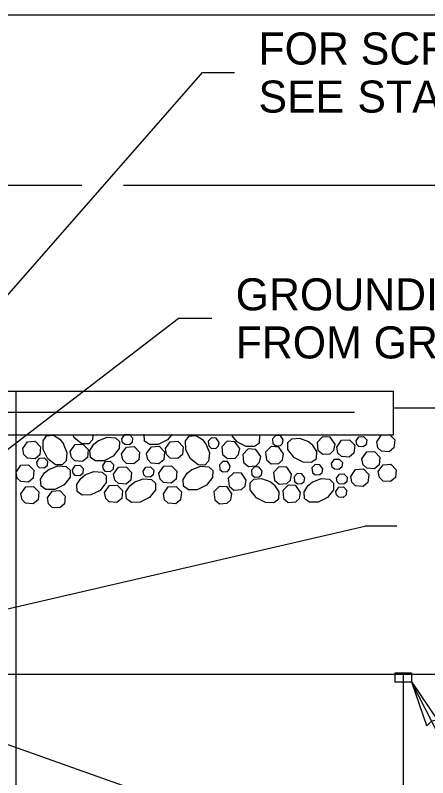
# Model space of a CAD drawing. Extents: x 99862 to 103680, y 99470 to 105076.
# Drawn here: x 100784.9 to 100991, y 104694.7 to 105075.5 of the extents above; entities that cross this region are included whole.
import ezdxf

# ---------------------------------------------------------------- set-up
doc = ezdxf.new("R2010")
doc.units = 0
for name, color, linetype in [('Level 1', 7, 'Continuous'), ('Level 12', 7, 'Continuous'), ('Level 15', 7, 'Continuous'), ('Level 16', 7, 'Continuous'), ('Level 20', 7, 'Continuous'), ('Level 3', 7, 'Continuous'), ('Level 33', 7, 'Continuous'), ('Level 6', 7, 'Continuous'), ('Level 9', 7, 'Continuous')]:
    doc.layers.add(name, color=color, linetype=linetype)

msp = doc.modelspace()

# ---------------------------------------------------------------- linework, layer by layer
at = {"layer": 'Level 1'}
msp.add_line((100343.64, 104887.78), (100943.64, 104887.78), dxfattribs=at)
msp.add_lwpolyline([(99862, 102999.5), (103151, 102999.5), (103151, 105075.5), (99862, 105075.5)], close=True, dxfattribs=at)
at = {"layer": 'Level 12'}
msp.add_lwpolyline([(100313.64, 104887.78), (100973.64, 104887.78), (100973.64, 104865.78), (100313.64, 104865.78)], close=True, dxfattribs=at)
at = {"layer": 'Level 15'}
for p, q in [((100760.56, 104912.34), (100878.43, 105046.89)), ((100878.43, 105046.89), (100894.43, 105046.89)), ((100675.26, 104777.56), (100866.25, 104924.12)), ((100883.04, 104924.12), (100866.25, 104924.12)), ((100706.3, 104761.84), (100959.51, 104820.29)), ((100975.51, 104820.29), (100959.51, 104820.29)), ((100693.13, 104742.4), (101012.2, 104629.58)), ((100982.9, 104742.4), (101012.2, 104684.93))]:
    msp.add_line(p, q, dxfattribs=at)
for points in [[(100617.42, 104990.65), (100818.24, 104990.65)], [(100839.05, 104990.65), (101204.8, 104990.65), (101435.21, 104856.14)]]:
    msp.add_lwpolyline(points, dxfattribs=at)
msp.add_lwpolyline([(100982.99, 104742.44), (100995.94, 104723.41), (100992.8, 104723.01), (100990.62, 104720.72)], close=True, dxfattribs=at)
at = {"layer": 'Level 16'}
for p, q in [((100785.34, 104392.87), (100785.34, 104887.78)), ((100246.62, 104746.39), (101041.91, 104746.39)), ((100978.89, 104392.86), (100978.89, 104746.39))]:
    msp.add_line(p, q, dxfattribs=at)
msp.add_lwpolyline([(100974.66, 104747.08), (100982.9, 104747.08), (100982.9, 104742.4), (100974.66, 104742.4)], close=True, dxfattribs=at)
at = {"layer": 'Level 3'}
for points in [[(100838.18, 104864), (100839.63, 104866.07), (100841.95, 104866.2), (100843.56, 104864.53), (100843.33, 104862.19), (100841.9, 104861), (100839.61, 104861.16), (100838.53, 104862.21), (100838.18, 104864)], [(100863.29, 104866.37), (100861.01, 104863.47), (100856.37, 104861.15), (100852.01, 104861.07), (100849.55, 104862.82), (100849.31, 104866.3), (100849.36, 104866.37)], [(100965.55, 104862.56), (100967.96, 104866), (100971.83, 104866.22), (100974.51, 104863.43), (100974.13, 104859.53), (100971.74, 104857.55), (100967.92, 104857.82), (100966.13, 104859.56), (100965.55, 104862.56)], [(100788.61, 104859.07), (100791.03, 104862.52), (100794.89, 104862.74), (100797.58, 104859.95), (100797.19, 104856.05), (100794.8, 104854.06), (100790.99, 104854.34), (100789.19, 104856.08), (100788.61, 104859.07)], [(100808.85, 104861.63), (100810.64, 104857.1), (100810.28, 104852.94), (100808.41, 104850.97), (100805.03, 104851.03), (100801.19, 104854.03), (100798.88, 104858.67), (100798.8, 104863.04), (100800.55, 104865.5), (100804.03, 104865.73), (100807.14, 104863.74), (100808.96, 104861.45)], [(100823.63, 104865.43), (100823.46, 104863.46), (100821.58, 104861.48), (100818.21, 104861.54), (100814.37, 104864.54), (100813.93, 104865.43)], [(100826.29, 104863.02), (100830.82, 104864.82), (100834.98, 104864.46), (100836.95, 104862.58), (100836.89, 104859.2), (100833.89, 104855.37), (100829.26, 104853.05), (100824.89, 104852.97), (100822.43, 104854.72), (100822.19, 104858.2), (100824.19, 104861.31), (100826.48, 104863.14)], [(100859.89, 104859.1), (100862.31, 104862.55), (100866.17, 104862.77), (100868.86, 104859.98), (100868.47, 104856.08), (100866.08, 104854.1), (100862.27, 104854.37), (100860.48, 104856.11), (100859.89, 104859.1)], [(100880.08, 104861.52), (100881.88, 104856.99), (100881.52, 104852.83), (100879.64, 104850.85), (100876.26, 104850.92), (100872.43, 104853.92), (100870.11, 104858.55), (100870.03, 104862.92), (100871.78, 104865.38), (100875.26, 104865.61), (100878.37, 104863.62), (100880.2, 104861.33)], [(100886.72, 104862.22), (100885.27, 104864.29), (100882.95, 104864.42), (100881.34, 104862.75), (100881.57, 104860.41), (100883.01, 104859.22), (100885.3, 104859.38), (100886.37, 104860.43), (100886.72, 104862.22)], [(100897.1, 104859.1), (100894.68, 104862.55), (100890.82, 104862.77), (100888.13, 104859.98), (100888.52, 104856.08), (100890.91, 104854.1), (100894.72, 104854.37), (100896.52, 104856.11), (100897.1, 104859.1)], [(100893.16, 104865.55), (100895.43, 104862.64), (100900.07, 104860.32), (100904.44, 104860.25), (100906.9, 104861.99), (100907.13, 104865.48), (100907.08, 104865.55)], [(100918.81, 104863.5), (100917.36, 104865.57), (100915.04, 104865.7), (100913.43, 104864.03), (100913.66, 104861.69), (100915.1, 104860.49), (100917.39, 104860.66), (100918.46, 104861.7), (100918.81, 104863.5)], [(100931.54, 104862.41), (100927.02, 104864.2), (100922.86, 104863.84), (100920.88, 104861.97), (100920.94, 104858.59), (100923.95, 104854.76), (100928.58, 104852.44), (100932.95, 104852.36), (100935.41, 104854.11), (100935.64, 104857.59), (100933.65, 104860.7), (100931.36, 104862.53)], [(100944.7, 104861.28), (100942.28, 104864.73), (100938.42, 104864.95), (100935.73, 104862.16), (100936.12, 104858.26), (100938.51, 104856.27), (100942.32, 104856.55), (100944.12, 104858.29), (100944.7, 104861.28)], [(100945.55, 104859.88), (100947.97, 104863.33), (100951.83, 104863.55), (100954.52, 104860.76), (100954.13, 104856.86), (100951.74, 104854.87), (100947.93, 104855.15), (100946.14, 104856.89), (100945.55, 104859.88)], [(100955.15, 104862.97), (100956.6, 104865.03), (100958.92, 104865.16), (100960.53, 104863.49), (100960.3, 104861.15), (100958.86, 104859.96), (100956.57, 104860.13), (100955.5, 104861.17), (100955.15, 104862.97)], [(100812.33, 104857.71), (100814.76, 104861.16), (100818.62, 104861.38), (100821.31, 104858.59), (100820.92, 104854.69), (100818.53, 104852.71), (100814.71, 104852.98), (100812.92, 104854.72), (100812.34, 104857.71)], [(100838.02, 104856.44), (100840.44, 104859.88), (100844.3, 104860.1), (100846.99, 104857.32), (100846.6, 104853.41), (100844.21, 104851.43), (100840.4, 104851.7), (100838.6, 104853.45), (100838.02, 104856.44)], [(100850.5, 104856.58), (100852.92, 104860.02), (100856.79, 104860.24), (100859.47, 104857.46), (100859.09, 104853.56), (100856.7, 104851.57), (100852.88, 104851.85), (100851.09, 104853.59), (100850.51, 104856.58)], [(100907.6, 104855.24), (100905.18, 104858.69), (100901.31, 104858.91), (100898.63, 104856.12), (100899.01, 104852.22), (100901.4, 104850.23), (100905.22, 104850.51), (100907.01, 104852.25), (100907.59, 104855.24)], [(100918.98, 104856.44), (100916.56, 104859.88), (100912.69, 104860.1), (100910.01, 104857.32), (100910.39, 104853.41), (100912.78, 104851.43), (100916.6, 104851.7), (100918.39, 104853.45), (100918.97, 104856.44)], [(100795.63, 104852.3), (100797.08, 104854.36), (100799.4, 104854.49), (100801.01, 104852.82), (100800.78, 104850.48), (100799.34, 104849.29), (100797.06, 104849.46), (100795.98, 104850.5), (100795.63, 104852.3)], [(100958.13, 104853.99), (100960.54, 104857.44), (100964.41, 104857.66), (100967.1, 104854.87), (100966.71, 104850.97), (100964.32, 104848.98), (100960.51, 104849.26), (100958.71, 104851), (100958.13, 104853.99)], [(100785.27, 104847.4), (100787.7, 104850.85), (100791.56, 104851.07), (100794.25, 104848.28), (100793.86, 104844.38), (100791.47, 104842.4), (100787.65, 104842.67), (100785.86, 104844.41), (100785.28, 104847.4)], [(100813.44, 104848.57), (100814.89, 104850.63), (100817.21, 104850.77), (100818.82, 104849.09), (100818.59, 104846.75), (100817.15, 104845.56), (100814.87, 104845.73), (100813.79, 104846.77), (100813.44, 104848.57)], [(100828.59, 104850.56), (100830.04, 104852.63), (100832.36, 104852.76), (100833.97, 104851.09), (100833.74, 104848.75), (100832.31, 104847.55), (100830.02, 104847.72), (100828.94, 104848.77), (100828.59, 104850.56)], [(100892.34, 104850.55), (100890.89, 104852.61), (100888.57, 104852.74), (100886.96, 104851.07), (100887.19, 104848.73), (100888.62, 104847.54), (100890.91, 104847.71), (100891.99, 104848.75), (100892.34, 104850.55)], [(100938.53, 104848.97), (100937.08, 104851.04), (100934.76, 104851.17), (100933.15, 104849.5), (100933.38, 104847.16), (100934.81, 104845.96), (100937.1, 104846.13), (100938.18, 104847.18), (100938.53, 104848.97)], [(100942.94, 104851.68), (100944.39, 104853.75), (100946.71, 104853.88), (100948.32, 104852.21), (100948.09, 104849.87), (100946.65, 104848.67), (100944.36, 104848.84), (100943.29, 104849.89), (100942.94, 104851.68)], [(100966.27, 104847.63), (100968.69, 104851.07), (100972.55, 104851.29), (100975.24, 104848.51), (100974.85, 104844.6), (100972.46, 104842.62), (100968.65, 104842.89), (100966.85, 104844.64), (100966.27, 104847.63)], [(100801.66, 104848.72), (100806.18, 104850.51), (100810.34, 104850.15), (100812.32, 104848.27), (100812.26, 104844.9), (100809.26, 104841.06), (100804.62, 104838.75), (100800.25, 104838.67), (100797.79, 104840.42), (100797.56, 104843.9), (100799.56, 104847.01), (100801.84, 104848.83)], [(100819.71, 104845.92), (100824.24, 104847.71), (100828.4, 104847.35), (100830.37, 104845.47), (100830.31, 104842.1), (100827.31, 104838.26), (100822.67, 104835.94), (100818.3, 104835.87), (100815.84, 104837.62), (100815.61, 104841.1), (100817.61, 104844.21), (100819.89, 104846.03)], [(100834.05, 104846.36), (100836.47, 104849.8), (100840.33, 104850.02), (100843.02, 104847.24), (100842.63, 104843.33), (100840.24, 104841.35), (100836.43, 104841.62), (100834.63, 104843.37), (100834.05, 104846.36)], [(100848.73, 104847.77), (100850.18, 104849.84), (100852.5, 104849.97), (100854.12, 104848.3), (100853.88, 104845.96), (100852.45, 104844.77), (100850.16, 104844.93), (100849.08, 104845.98), (100848.73, 104847.77)], [(100856.66, 104846.88), (100859.08, 104850.32), (100862.95, 104850.54), (100865.63, 104847.76), (100865.25, 104843.86), (100862.86, 104841.87), (100859.04, 104842.15), (100857.25, 104843.89), (100856.67, 104846.88)], [(100872.9, 104848.56), (100877.43, 104850.36), (100881.59, 104850), (100883.57, 104848.12), (100883.51, 104844.74), (100880.51, 104840.91), (100875.87, 104838.59), (100871.5, 104838.51), (100869.04, 104840.26), (100868.81, 104843.74), (100870.8, 104846.85), (100873.09, 104848.68)], [(100900.33, 104843.39), (100897.91, 104846.84), (100894.04, 104847.06), (100891.36, 104844.27), (100891.75, 104840.37), (100894.13, 104838.38), (100897.95, 104838.66), (100899.75, 104840.4), (100900.33, 104843.39)], [(100908.26, 104847.77), (100906.81, 104849.84), (100904.49, 104849.97), (100902.88, 104848.3), (100903.11, 104845.96), (100904.54, 104844.77), (100906.83, 104844.93), (100907.91, 104845.98), (100908.26, 104847.77)], [(100922.95, 104846.36), (100920.52, 104849.8), (100916.66, 104850.02), (100913.97, 104847.24), (100914.36, 104843.33), (100916.75, 104841.35), (100920.57, 104841.62), (100922.36, 104843.37), (100922.94, 104846.36)], [(100952.54, 104845.25), (100954.96, 104848.7), (100958.83, 104848.92), (100961.51, 104846.13), (100961.12, 104842.23), (100958.74, 104840.24), (100954.92, 104840.52), (100953.13, 104842.26), (100952.54, 104845.25)], [(100844.31, 104842.26), (100848.83, 104844.05), (100852.99, 104843.69), (100854.97, 104841.81), (100854.91, 104838.44), (100851.91, 104834.6), (100847.27, 104832.28), (100842.9, 104832.21), (100840.44, 104833.95), (100840.21, 104837.44), (100842.2, 104840.55), (100844.49, 104842.37)], [(100912.69, 104842.26), (100908.16, 104844.05), (100904, 104843.69), (100902.02, 104841.81), (100902.09, 104838.44), (100905.09, 104834.6), (100909.72, 104832.28), (100914.09, 104832.21), (100916.55, 104833.95), (100916.79, 104837.44), (100914.79, 104840.55), (100912.5, 104842.37)], [(100929.57, 104844.49), (100928.11, 104846.56), (100925.79, 104846.69), (100924.18, 104845.02), (100924.42, 104842.68), (100925.85, 104841.49), (100928.14, 104841.65), (100929.21, 104842.7), (100929.56, 104844.49)], [(100933.27, 104842.36), (100937.8, 104844.16), (100941.96, 104843.8), (100943.94, 104841.92), (100943.87, 104838.54), (100940.87, 104834.71), (100936.24, 104832.39), (100931.87, 104832.31), (100929.41, 104834.06), (100929.17, 104837.54), (100931.17, 104840.65), (100933.46, 104842.48)], [(100945.37, 104844.35), (100946.83, 104846.41), (100949.14, 104846.54), (100950.76, 104844.87), (100950.52, 104842.53), (100949.09, 104841.34), (100946.8, 104841.51), (100945.72, 104842.55), (100945.38, 104844.35)], [(100787.71, 104836.57), (100790.13, 104840.02), (100793.99, 104840.24), (100796.68, 104837.45), (100796.29, 104833.55), (100793.9, 104831.56), (100790.09, 104831.84), (100788.29, 104833.58), (100787.71, 104836.57)], [(100829.49, 104837.25), (100831.91, 104840.69), (100835.78, 104840.91), (100838.47, 104838.13), (100838.08, 104834.22), (100835.69, 104832.24), (100831.87, 104832.52), (100830.08, 104834.26), (100829.5, 104837.25)], [(100858.94, 104836.57), (100861.36, 104840.02), (100865.23, 104840.24), (100867.91, 104837.45), (100867.52, 104833.55), (100865.14, 104831.56), (100861.32, 104831.84), (100859.53, 104833.58), (100858.94, 104836.57)], [(100893.13, 104836.57), (100890.71, 104840.02), (100886.84, 104840.24), (100884.16, 104837.45), (100884.55, 104833.55), (100886.93, 104831.56), (100890.75, 104831.84), (100892.54, 104833.58), (100893.13, 104836.57)], [(100927.5, 104837.25), (100925.08, 104840.69), (100921.22, 104840.91), (100918.53, 104838.13), (100918.92, 104834.22), (100921.3, 104832.24), (100925.12, 104832.52), (100926.91, 104834.26), (100927.5, 104837.25)], [(100945.09, 104837.75), (100946.55, 104839.82), (100948.86, 104839.95), (100950.48, 104838.28), (100950.24, 104835.94), (100948.81, 104834.75), (100946.52, 104834.91), (100945.44, 104835.96), (100945.1, 104837.75)], [(100800.94, 104834.47), (100803.36, 104837.91), (100807.22, 104838.13), (100809.91, 104835.34), (100809.52, 104831.44), (100807.13, 104829.45), (100803.32, 104829.73), (100801.53, 104831.47), (100800.94, 104834.46)]]:
    msp.add_lwpolyline(points, dxfattribs=at)
at = {"layer": 'Level 33'}
msp.add_line((100329.67, 104877.22), (100954.38, 104877.22), dxfattribs=at)
at = {"layer": 'Level 6'}
msp.add_line((101042.88, 104879.24), (100973.93, 104879.24), dxfattribs=at)
at = {"layer": 'Level 9'}
msp.add_lwpolyline([(100974.73, 104747.04), (100982.9, 104747.04), (100982.9, 104742.42), (100974.73, 104742.42)], close=True, dxfattribs=at)

# ---------------------------------------------------------------- texts
at = {"layer": 'Level 20'}
for s, p in [('FOR SCREEN GUARD DETAILS  ', (100906.43, 105050.89)), ('SEE', (100906.43, 105026.89)), (' STANDARD PLAN J-29.10', (100949.91, 105026.89)), ('GROUNDING CONDUCTOR ', (100895.04, 104928.12)), ('FROM GROUND RING', (100895.04, 104904.12))]:
    msp.add_text(s, height=16, dxfattribs=at).set_placement(p)

doc.saveas('drawing.dxf')
